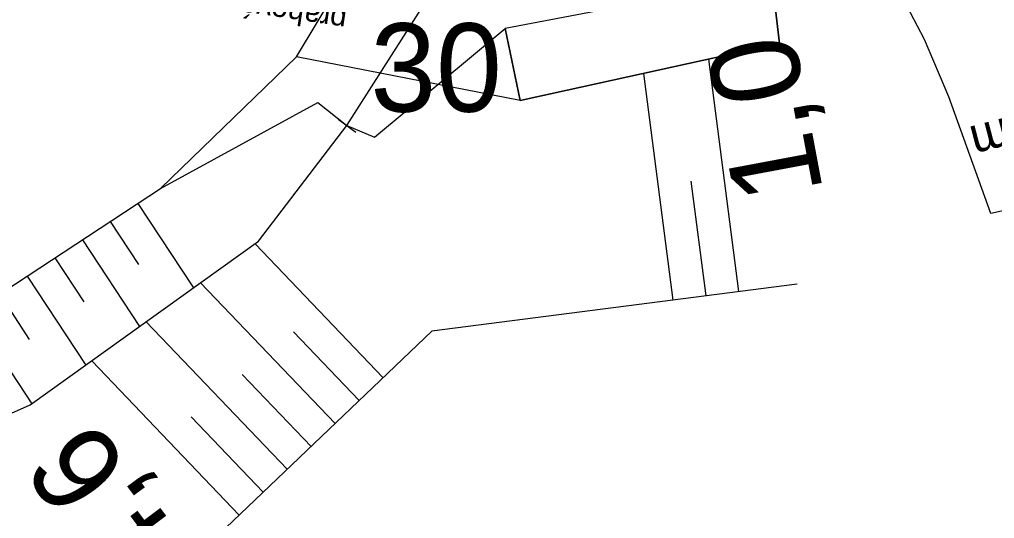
# Model space of a CAD drawing. Extents: x -806456 to -805395, y -1150847 to -1150506.
# Drawn here: x -806177.4 to -806155.34, y -1150729.51 to -1150718.21 of the extents above; entities that cross this region are included whole.
import ezdxf

# ---------------------------------------------------------------- set-up
doc = ezdxf.new("R2010")
doc.units = 0
for name, color, linetype in [('0-odvodnění popisy', 7, 'Continuous'), ('0-podelny_profil_popis', 7, 'Continuous'), ('0-Trativody+svodna_potrubi', 7, 'Continuous'), ('0381KM032-037P - Vrstva 16', 7, 'Continuous'), ('0381KM032-037P - Vrstva 19', 7, 'Continuous'), ('0381KM032-037P - Vrstva 48', 7, 'Continuous'), ('0381KM032-037P - Vrstva 49', 7, 'Continuous'), ('0381KM032-037P - Vrstva 51', 7, 'Continuous'), ('lomové body', 7, 'Continuous')]:
    doc.layers.add(name, color=color, linetype=linetype)

msp = doc.modelspace()

# ---------------------------------------------------------------- linework, layer by layer
at = {"layer": '0-Trativody+svodna_potrubi'}
msp.add_line((-806169.987, -1150720.615), (-806157.733, -1150701.3), dxfattribs=at)
at = {"layer": '0381KM032-037P - Vrstva 16'}
for p, q in [((-806160.478, -1150717.283), (-806166.409, -1150718.419)), ((-806160.198, -1150718.758), (-806160.293, -1150717.983)), ((-806166.409, -1150718.419), (-806166.069, -1150720.047)), ((-806166.069, -1150720.047), (-806160.198, -1150718.758))]:
    msp.add_line(p, q, dxfattribs=at)
msp.add_lwpolyline([(-806166.069, -1150720.047), (-806171.128, -1150719.056), (-806168.37, -1150714.464), (-806166.085, -1150714.657), (-806164.602, -1150713.817)], dxfattribs=at)
at = {"layer": '0381KM032-037P - Vrstva 19'}
for p, q in [((-806169.987, -1150720.615), (-806157.733, -1150701.3)), ((-806170.188, -1150720.467), (-806169.786, -1150720.763))]:
    msp.add_line(p, q, dxfattribs=at)
at = {"layer": '0381KM032-037P - Vrstva 48'}
for p, q in [((-806161.12, -1150724.375), (-806161.801, -1150719.11)), ((-806162.608, -1150724.567), (-806163.272, -1150719.433)), ((-806161.864, -1150724.471), (-806162.2, -1150721.871)), ((-806174.716, -1150722.377), (-806173.459, -1150724.29)), ((-806175.343, -1150722.788), (-806174.706, -1150723.758)), ((-806175.97, -1150723.2), (-806174.679, -1150725.165)), ((-806169.169, -1150726.326), (-806172.068, -1150723.292)), ((-806176.597, -1150723.612), (-806175.943, -1150724.607)), ((-806177.223, -1150724.024), (-806175.899, -1150726.04)), ((-806170.253, -1150727.362), (-806173.299, -1150724.175)), ((-806177.85, -1150724.435), (-806177.18, -1150725.456)), ((-806178.477, -1150724.847), (-806177.119, -1150726.915)), ((-806171.338, -1150728.398), (-806174.53, -1150725.058)), ((-806169.711, -1150726.844), (-806171.197, -1150725.288)), ((-806172.423, -1150729.435), (-806175.761, -1150725.941)), ((-806170.796, -1150727.88), (-806172.355, -1150726.248)), ((-806171.88, -1150728.916), (-806173.513, -1150727.208))]:
    msp.add_line(p, q, dxfattribs=at)
at = {"layer": '0381KM032-037P - Vrstva 49'}
for points in [[(-806086.941, -1150691.888), (-806103.092, -1150696.78), (-806110.097, -1150699.269), (-806113.941, -1150700.3), (-806116.978, -1150701.29), (-806117.569, -1150702.15), (-806117.466, -1150702.7), (-806118.52, -1150712.146), (-806144.328, -1150720.147), (-806155.423, -1150722.604), (-806156.372, -1150719.964), (-806156.921, -1150718.664), (-806157.558, -1150717.448), (-806160.478, -1150717.283), (-806160.293, -1150717.983), (-806160.198, -1150718.758), (-806166.069, -1150720.047), (-806166.409, -1150718.419)], [(-806169.987, -1150720.615), (-806169.362, -1150720.879), (-806166.409, -1150718.419)], [(-806174.208, -1150722.043), (-806170.645, -1150720.091), (-806169.987, -1150720.615)], [(-806193.249, -1150733.077), (-806185.745, -1150730.772), (-806177.154, -1150726.94), (-806171.988, -1150723.234), (-806169.987, -1150720.615)], [(-806194.182, -1150731.583), (-806186.226, -1150728.982), (-806178.594, -1150724.924), (-806174.208, -1150722.043)], [(-806159.8, -1150724.204), (-806168.067, -1150725.273), (-806174.063, -1150731.002)]]:
    msp.add_lwpolyline(points, dxfattribs=at)
at = {"layer": '0381KM032-037P - Vrstva 51'}
msp.add_lwpolyline([(-806194.182, -1150731.583), (-806186.226, -1150728.982), (-806178.594, -1150724.924), (-806174.208, -1150722.043), (-806171.128, -1150719.056), (-806168.37, -1150714.464), (-806165.452, -1150708.868), (-806162.708, -1150704.236), (-806160.94, -1150702.044), (-806159.44, -1150700.497), (-806157.039, -1150698.345), (-806150.424, -1150694.243), (-806141.479, -1150690.749), (-806131.125, -1150687.358), (-806121.483, -1150684.155)], dxfattribs=at)

# ---------------------------------------------------------------- texts
at = {"layer": '0-odvodnění popisy'}
msp.add_text('prahová vpust', height=0.5, rotation=171.5137, dxfattribs=at).set_placement((-806169.968, -1150717.998))
at = {"layer": '0-podelny_profil_popis'}
msp.add_text('Rv=2000m', height=0.8, rotation=194.6365, dxfattribs=at).set_placement((-806150.914, -1150719.338))
at = {"layer": '0381KM032-037P - Vrstva 48'}
for s, rotation, p in [('1,0', 100.6308, (-806159.21, -1150722.113)), ('4,6', 126.74, (-806173.521, -1150730.195))]:
    msp.add_text(s, height=2, rotation=rotation, dxfattribs=at).set_placement(p)
at = {"layer": 'lomové body'}
msp.add_text(' 30', height=2, dxfattribs=at).set_placement((-806170.201, -1150720.3))

doc.saveas('drawing.dxf')
